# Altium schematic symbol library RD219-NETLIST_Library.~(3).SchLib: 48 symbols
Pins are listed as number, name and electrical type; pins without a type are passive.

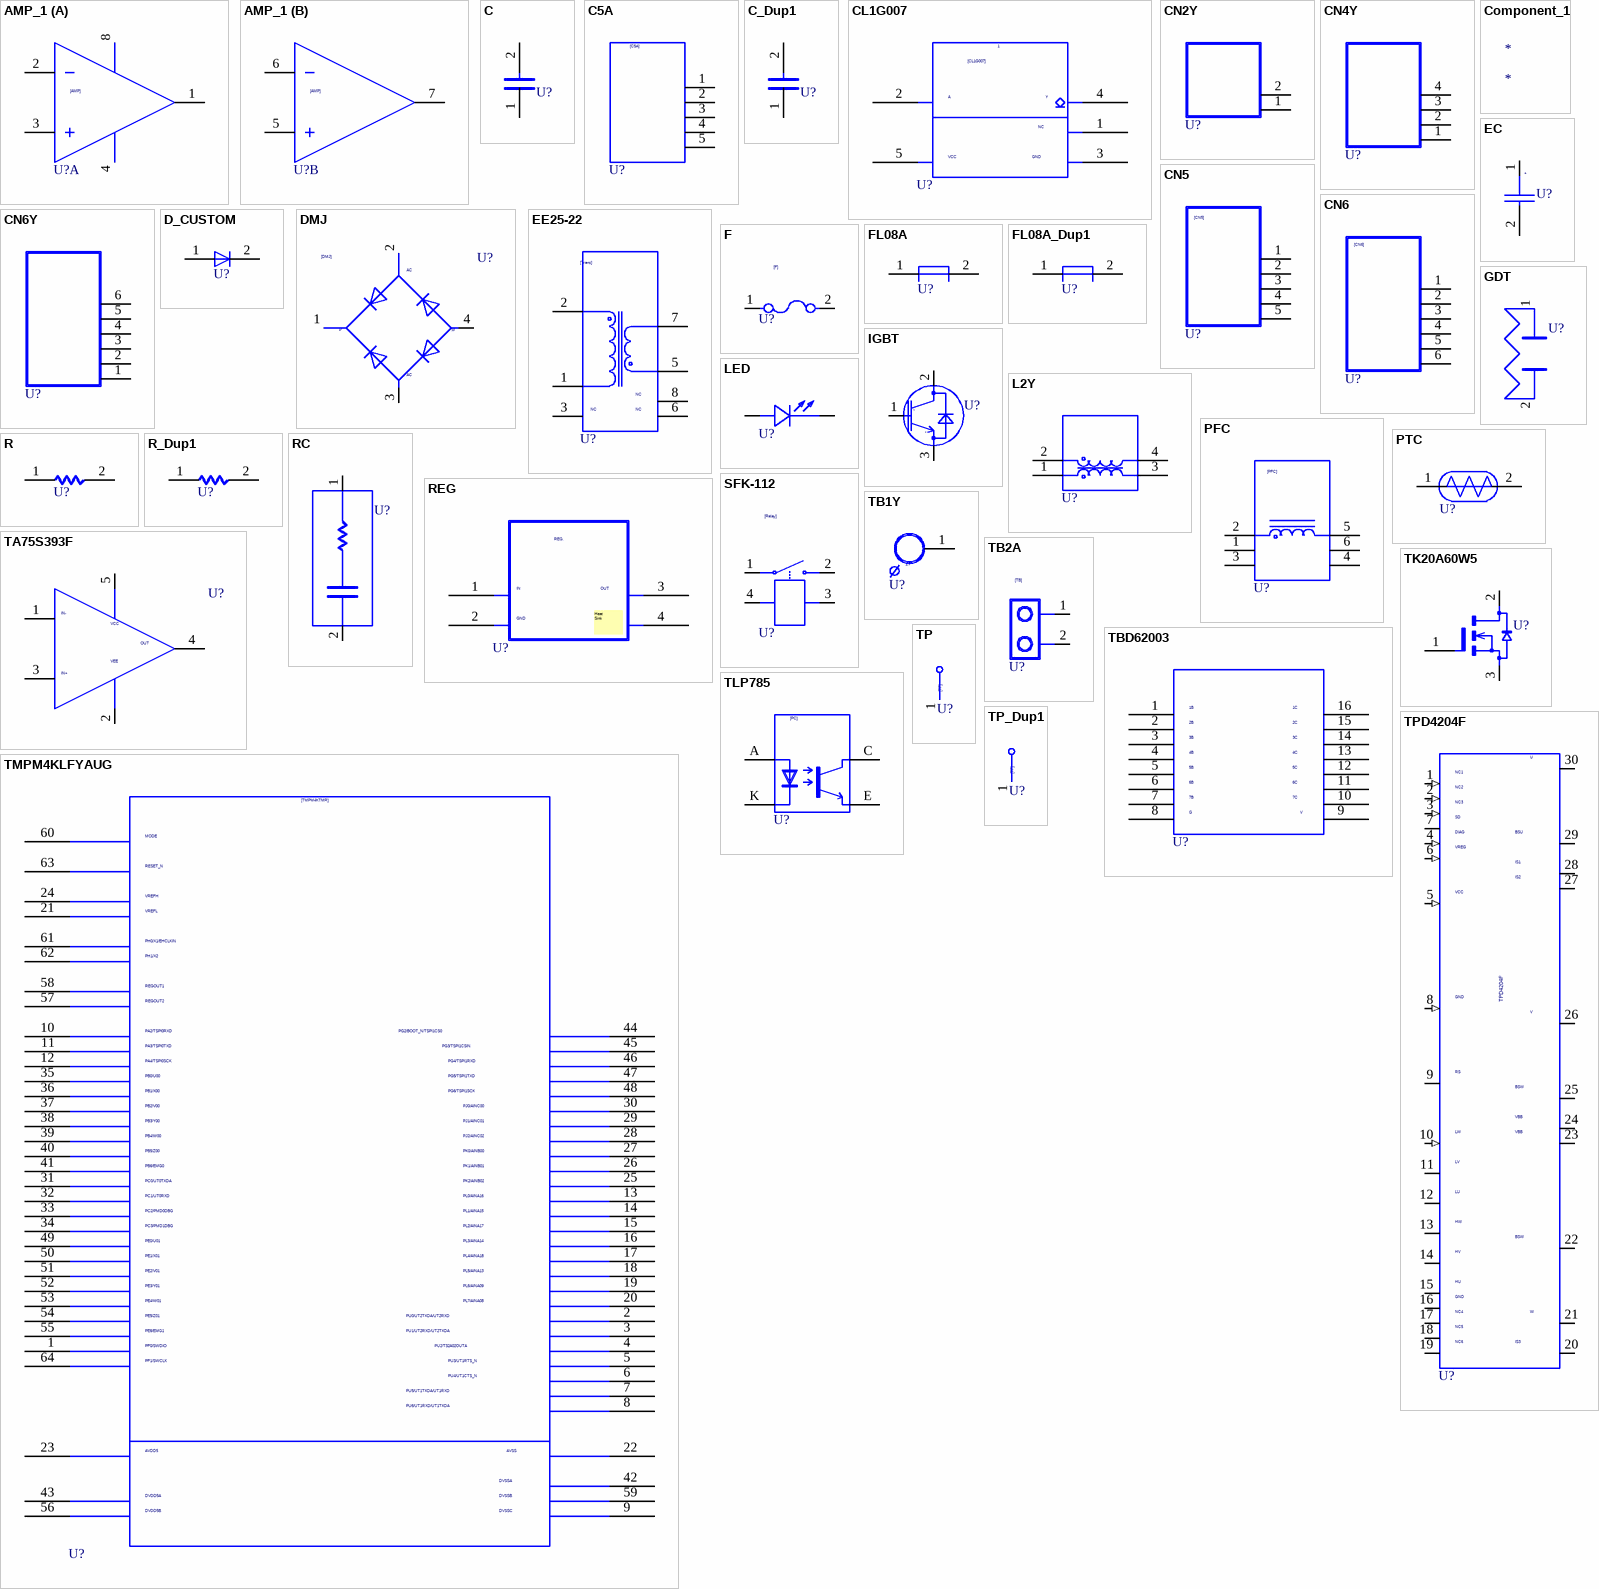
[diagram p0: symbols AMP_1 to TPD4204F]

## AMP_1
designator U?  (value not drawn)
SAVEAREA0: -6226,-235,36343,20943; TIME: 17:09:52; UPDATEUSER: w20165dm; SAVECOUNT: 1; OriginalSymbolOrigin: (5080,20320); Altium-Right: 80
part A pins: 1, 2, 3, 4, 8
part B pins: 5, 6, 7

## C
designator U?  (value not drawn)
OriginalSymbolOrigin: (2540,7620); Altium-Right: 20; Altium-Bottom: 10
pins: 1, 2

## C5A
designator U?  (value not drawn)
SAVEAREA0: -9193,-269,29123,23485; TIME: 08:44:29; UPDATEUSER: fukuda-y; UPDATETIME: 10:06:49; SAVECOUNT: 4; OriginalSymbolOrigin: (2540,20320); Altium-Right: 50; Altium-Bottom: 80
pins: 1, 2, 3, 4, 5

## C_Dup1
designator U?, comment C  (value not drawn)
OriginalSymbolOrigin: (2540,7620); Altium-Right: 20; Altium-Bottom: 10
pins: 1, 2

## CL1G007
designator U?  (value not drawn)
TIME: 15:16:30; UPDATEUSER: 19990028; UPDATETIME: 09:49:48; SAVECOUNT: 10; SAVEAREA0: -1829,-329,45053,28196; OriginalSymbolOrigin: (7620,25400); Altium-Right: 110; Altium-Bottom: 90
pins: 1, 2, 3, 4, 5

## CN2Y
designator U?  (value not drawn)
SAVEAREA0: -6573,-310,26384,16086; TIME: 09:52:32; UPDATEUSER: w20165dm; SAVECOUNT: 1; OriginalSymbolOrigin: (2540,15240); Altium-Right: 50; Altium-Bottom: 60
pins: 1, 2

## CN4Y
designator U?  (value not drawn)
SAVEAREA0: -5115,-437,24748,21425; TIME: 09:53:19; UPDATEUSER: w20165dm; SAVECOUNT: 1; OriginalSymbolOrigin: (2540,20320); Altium-Right: 50; Altium-Bottom: 80
pins: 1, 2, 3, 4

## CN5
designator U?  (value not drawn)
OriginalSymbolOrigin: (2540,22860); Altium-Right: 50; Altium-Bottom: 90
pins: 1, 2, 3, 4, 5

## CN6
designator U?  (value not drawn)
OriginalSymbolOrigin: (2540,25400); Altium-Right: 50; Altium-Bottom: 100
pins: 1, 2, 3, 4, 5, 6

## CN6Y
designator U?  (value not drawn)
SAVEAREA0: -8909,-546,28423,26783; TIME: 09:54:13; UPDATEUSER: w20165dm; SAVECOUNT: 1; OriginalSymbolOrigin: (2540,25400); Altium-Right: 50; Altium-Bottom: 100
pins: 1, 2, 3, 4, 5, 6

## Component_1
designator *

## D_CUSTOM
designator U?  (value not drawn)
SAVEAREA0: -1668,-97,14265,7829; SAVECOUNT: 4; TIME: 14:49:55; UPDATEUSER: w20165dm; UPDATETIME: 16:47:49; OriginalSymbolOrigin: (5080,5080); Altium-Right: 10; Altium-Bottom: 20
pins: 1, 2

## DMJ
designator U?  (value not drawn)
SAVECOUNT: 10; SAVEAREA0: -26809,-16062,52116,41716; TIME: 10:09:47; UPDATEUSER: sptcae13; UPDATETIME: 17:23:53; OriginalSymbolOrigin: (0,25400); Altium-Right: 90
pins: 1, 2, 3, 4

## EC
designator U?  (value not drawn)
SAVEAREA0: -1432,-1528,20311,14389; SAVECOUNT: 53; TIME: 15:02:55; UPDATEUSER: w20165dm; UPDATETIME: 16:35:05; OriginalSymbolOrigin: (2540,10160); Altium-Right: 20
pins: 1, 2

## EE25-22
designator U?  (value not drawn)
TIME: 15:54:32; UPDATEUSER: sptcae13; UPDATETIME: 17:21:25; SAVECOUNT: 10; SAVEAREA0: -19028,-5512,41701,38945; OriginalSymbolOrigin: (5080,30480); Altium-Right: 50; Altium-Bottom: 120
pins: 1, 2, 3, 5, 6, 7, 8

## F
designator U?  (value not drawn)
OriginalSymbolOrigin: (2540,5080); Altium-Right: 40; Altium-Bottom: 20
pins: 1, 2

## FL08A
designator U?  (value not drawn)
SAVEAREA0: -112,-1299,15373,8886; TIME: 08:53:27; UPDATEUSER: kishi-s; UPDATETIME: 15:03:21; SAVECOUNT: 4; OriginalSymbolOrigin: (5080,5080); Altium-Right: 20
pins: 1, 2

## FL08A_Dup1
designator U?, comment FL08A  (value not drawn)
SAVEAREA0: -112,-1299,15373,8886; TIME: 08:53:27; UPDATEUSER: kishi-s; UPDATETIME: 15:03:21; SAVECOUNT: 4; OriginalSymbolOrigin: (5080,5080); Altium-Right: 20
pins: 1, 2

## GDT
designator U?  (value not drawn)
TIME: 16:28:26; UPDATEUSER: w20165dm; UPDATETIME: 16:32:17; SAVECOUNT: 3; SAVEAREA0: -9109,-176,22817,15707; OriginalSymbolOrigin: (0,15240); Altium-Right: 30; Altium-Bottom: 60
pins: 1, 2

## IGBT
designator U?  (value not drawn)
TIME: 09:39:04; UPDATEUSER: sptcae13; UPDATETIME: 17:26:37; SAVECOUNT: 12; SAVEAREA0: -8366,-3926,23558,19444; OriginalSymbolOrigin: (2540,12700); Altium-Right: 50; Altium-Bottom: 40
pins: 1, 2, 3

## L2Y
designator U?  (value not drawn)
SAVEAREA0: -7346,-206,29901,18324; TIME: 15:13:45; UPDATEUSER: w20165dm; SAVECOUNT: 1; OriginalSymbolOrigin: (5080,15240); Altium-Right: 50
pins: 1, 2, 3, 4

## LED
designator U?  (value not drawn)
TIME: 09:29:00; UPDATEUSER: sptcae13; UPDATETIME: 17:03:31; SAVECOUNT: 2; SAVEAREA0: -3132,-7866,12954,3909; OriginalSymbolOrigin: (0,0); Altium-Right: 40; Altium-Bottom: 20
pins: 1, 2

## PFC
designator U?  (value not drawn)
SAVEAREA0: -15388,-294,37822,26178; TIME: 13:55:27; UPDATEUSER: w20165dm; SAVECOUNT: 1; OriginalSymbolOrigin: (5080,22860); Altium-Right: 50; Altium-Bottom: 80
pins: 1, 2, 3, 4, 5, 6

## PTC
designator U?  (value not drawn)
TIME: 17:09:47; UPDATEUSER: w20165dm; UPDATETIME: 17:16:29; SAVECOUNT: 2; SAVEAREA0: -4525,-147,22079,13088; OriginalSymbolOrigin: (5080,7620); Altium-Right: 30; Altium-Bottom: 20
pins: 1, 2

## R
designator U?  (value not drawn)
OriginalSymbolOrigin: (5080,5080); Altium-Right: 20
pins: 1, 2

## R_Dup1
designator U?, comment R  (value not drawn)
OriginalSymbolOrigin: (5080,5080); Altium-Right: 20
pins: 1, 2

## RC
designator U?  (value not drawn)
SAVEAREA0: -17024,-284,34362,28697; TIME: 17:42:57; UPDATEUSER: w20165dm; UPDATETIME: 17:46:02; SAVECOUNT: 2; OriginalSymbolOrigin: (2540,25400); Altium-Right: 40; Altium-Bottom: 90
pins: 1, 2

## REG
designator U?  (value not drawn)
SAVEAREA0: -5753,-289,46434,25674; SAVECOUNT: 4; TIME: 17:36:06; UPDATEUSER: w20165dm; UPDATETIME: 17:45:44; OriginalSymbolOrigin: (7620,22860); Altium-Right: 100; Altium-Bottom: 80
pins: 1, 2, 3, 4

## SFK-112
designator U?  (value not drawn)
SAVEAREA0: -13231,-231,28521,20540; TIME: 14:06:16; UPDATEUSER: w20165dm; UPDATETIME: 17:57:42; SAVECOUNT: 24; OriginalSymbolOrigin: (2540,12700); Altium-Right: 40; Altium-Bottom: 50
pins: 1, 2, 3, 4

## TA75S393F
designator U?  (value not drawn)
SAVECOUNT: 22; SAVEAREA0: -11585,-294,41625,26178; TIME: 20:02:00; UPDATEUSER: w20165dm; UPDATETIME: 20:02:39; OriginalSymbolOrigin: (5080,22860); Altium-Right: 80
pins: 1, 2, 3, 4, 5

## TB1Y
designator U?  (value not drawn)
SAVEAREA0: -4386,-117,16897,10471; TIME: 15:17:35; UPDATEUSER: w20165dm; UPDATETIME: 16:46:01; SAVECOUNT: 2; OriginalSymbolOrigin: (0,7620); Altium-Right: 30
pins: 1

## TB2A
designator U?  (value not drawn)
SAVEAREA0: -12188,-370,24974,18118; TIME: 11:16:32; UPDATEUSER: w20165dm; UPDATETIME: 16:47:04; SAVECOUNT: 2; OriginalSymbolOrigin: (2540,12700); Altium-Right: 30; Altium-Bottom: 40
pins: 1, 2

## TBD62003
designator U?  (value not drawn)
SAVECOUNT: 34; SAVEAREA0: -8546,-383,48557,34032; TIME: 11:13:04; UPDATEUSER: w20165dm; UPDATETIME: 19:36:15; OriginalSymbolOrigin: (7620,30480); Altium-Right: 100; Altium-Bottom: 110
pins: 1, 2, 3, 4, 5, 6, 7, 8, 9, 10, 11, 12, 13, 14, 15, 16

## TK20A60W5
designator U?  (value not drawn)
SAVECOUNT: 14; SAVEAREA0: -8366,-3926,23558,19444; TIME: 13:50:47; UPDATEUSER: sptcae13; UPDATETIME: 17:26:54; OriginalSymbolOrigin: (5080,12700); Altium-Right: 40
pins: 1, 2, 3

## TLP785
designator U?  (value not drawn)
SAVEAREA0: -3804,-437,26060,21425; TIME: 09:38:30; UPDATEUSER: w20165dm; SAVECOUNT: 1; OriginalSymbolOrigin: (5080,17780); Altium-Right: 50; Altium-Bottom: 70
pins: A, C, E, K

## TMPM4KLFYAUG
designator U?  (value not drawn)
SAVEAREA0: -81909,-1350,188872,133365; TIME: 14:58:35; UPDATEUSER: w20165dm; UPDATETIME: 11:11:19; SAVECOUNT: 16; OriginalSymbolOrigin: (7620,129540); Altium-Right: 360; Altium-Bottom: 500
pins: 1, 2, 3, 4, 5, 6, 7, 8, 9, 10, 11, 12, 13, 14, 15, 16, 17, 18, 19, 20, 21, 22, 23, 24, 25, 26, 27, 28, 29, 30, 31, 32, 33, 34, 35, 36, 37, 38, 39, 40, 41, 42, 43, 44, 45, 46, 47, 48, 49, 50, 51, 52, 53, 54, 55, 56, 57, 58, 59, 60, 61, 62, 63, 64

## TP
designator U?  (value not drawn)
TIME: 16:12:21; UPDATEUSER: fukuda-y; UPDATETIME: 16:18:11; SAVECOUNT: 2; SAVEAREA0: -242,-92,12810,7836; OriginalSymbolOrigin: (0,7620); Altium-Right: 20; Altium-Bottom: 30
pins: 1

## TP_Dup1
designator U?, comment TP  (value not drawn)
TIME: 16:12:21; UPDATEUSER: fukuda-y; UPDATETIME: 16:18:11; SAVECOUNT: 2; SAVEAREA0: -242,-92,12810,7836; OriginalSymbolOrigin: (0,7620); Altium-Right: 20; Altium-Bottom: 30
pins: 1

## TPD4204F
designator U?  (value not drawn)
TIME: 16:32:01; UPDATEUSER: sptcae13; UPDATETIME: 10:27:40; SAVECOUNT: 16; SAVEAREA0: -113524,-1329,136787,112726; OriginalSymbolOrigin: (2540,106680); Altium-Right: 80; Altium-Bottom: 410
pins: 1 (in), 2 (in), 3 (in), 4 (in), 5 (in), 6 (in), 7, 8 (in), 9, 10 (in), 11, 12, 13, 14, 15, 16, 17, 18, 19, 20, 21, 22, 23, 24, 25, 26, 27, 28, 29, 30

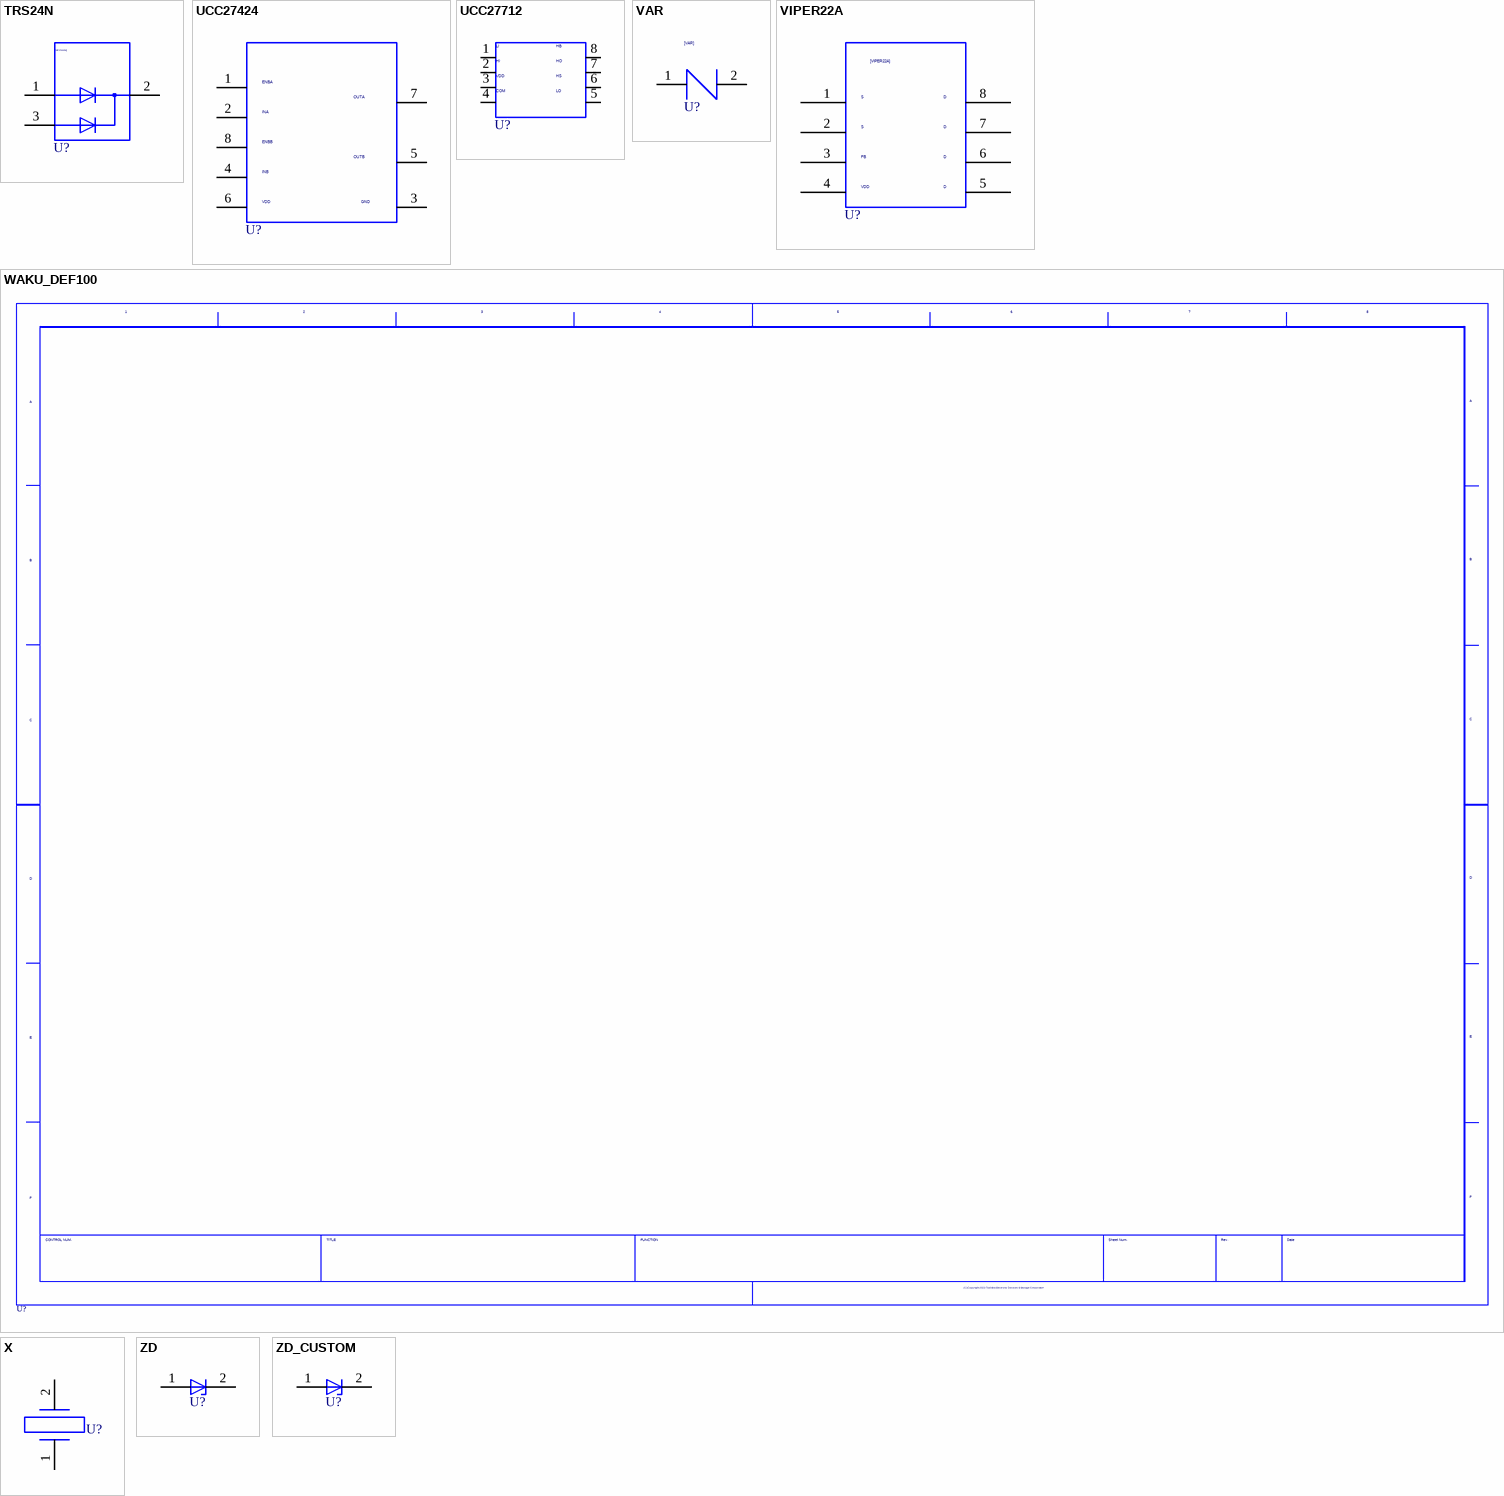
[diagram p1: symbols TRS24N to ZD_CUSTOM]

## TRS24N
designator U?  (value not drawn)
SAVEAREA0: -10023,-235,32546,20943; TIME: 17:15:17; UPDATEUSER: w20165dm; SAVECOUNT: 1; OriginalSymbolOrigin: (5080,20320); Altium-Right: 50; Altium-Bottom: 70
pins: 1, 2, 3

## UCC27424
designator U?  (value not drawn)
SAVEAREA0: -18701,-404,54363,35945; TIME: 14:53:37; UPDATEUSER: w20165dm; UPDATETIME: 17:37:13; SAVECOUNT: 7; OriginalSymbolOrigin: (5080,33020); Altium-Right: 100; Altium-Bottom: 120
pins: 1, 2, 3, 4, 5, 6, 7, 8

## UCC27712
designator U?  (value not drawn)
COMPTYPERIPPER: Y; TIME: 09:28:59; UPDATEUSER: sptcae13; UPDATETIME: 09:18:42; SAVECOUNT: 4; SAVEAREA0: -15749,-25534,36467,12691; OriginalSymbolOrigin: (2540,0); Altium-Right: 60; Altium-Bottom: 50
pins: 1, 2, 3, 4, 5, 6, 7, 8

## VAR
designator U?  (value not drawn)
SAVEAREA0: -418,-1801,15408,7141; SAVECOUNT: 5; OriginalSymbolOrigin: (5080,5080); Altium-Right: 20
pins: 1, 2

## VIPER22A
designator U?  (value not drawn)
SAVEAREA0: -16087,-375,51758,33378; SAVECOUNT: 16; TIME: 11:13:15; UPDATEUSER: w20165dm; UPDATETIME: 13:40:21; OriginalSymbolOrigin: (7620,30480); Altium-Right: 80; Altium-Bottom: 110
pins: 1, 2, 3, 4, 5, 6, 7, 8

## WAKU_DEF100
designator U?  (value not drawn)
PLOTTIME: HH:MM; SAVEAREA0: 185750,-43960,448537,75779; TIME: 14:30:25; UPDATEUSER: PS4_common_PC; UPDATETIME: 14:13:01; SAVECOUNT: 8; OriginalSymbolOrigin: (10160,284480); Altium-Right: 1570; Altium-Bottom: 1070

## X
designator U?  (value not drawn)
SAVEAREA0: -5556,-184,20536,15665; TIME: 10:12:32; UPDATEUSER: fukuda-y; SAVECOUNT: 1; OriginalSymbolOrigin: (0,10160); Altium-Right: 40; Altium-Bottom: 20
pins: 1, 2

## ZD
designator U?  (value not drawn)
SAVEAREA0: -4630,-153,17114,13055; TIME: 14:49:55; UPDATEUSER: fukuda-y; UPDATETIME: 08:18:42; SAVECOUNT: 6; OriginalSymbolOrigin: (5080,5080); Altium-Right: 10; Altium-Bottom: 20
pins: 1 A, 2 C

## ZD_CUSTOM
designator U?  (value not drawn)
SAVEAREA0: -4071,-115,16804,10270; TIME: 09:43:08; UPDATEUSER: w20165dm; UPDATETIME: 16:32:57; SAVECOUNT: 4; OriginalSymbolOrigin: (5080,5080); Altium-Right: 10; Altium-Bottom: 20
pins: 1, 2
